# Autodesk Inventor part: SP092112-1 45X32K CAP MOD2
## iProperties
Created: 2007-01
Part Number: SP092112-1 45X32K CAP MOD2
Document SubType Name: Modeling
Designer: Andy Moles
Material: ABS Plastic
Density: 1.06 g/cm^3
Mass: 4.46297 g
Surface Area: 35.8055 cm^2
Volume: 4.21035 cm^3
Author: Andy Moles
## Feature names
1. Extrusion1
2. Fillet1
3. Fillet2
4. Extrusion2
5. Extrusion3
6. Fillet3
7. Extrusion4
8. Fillet4
9. Extrusion6
10. Fillet6
